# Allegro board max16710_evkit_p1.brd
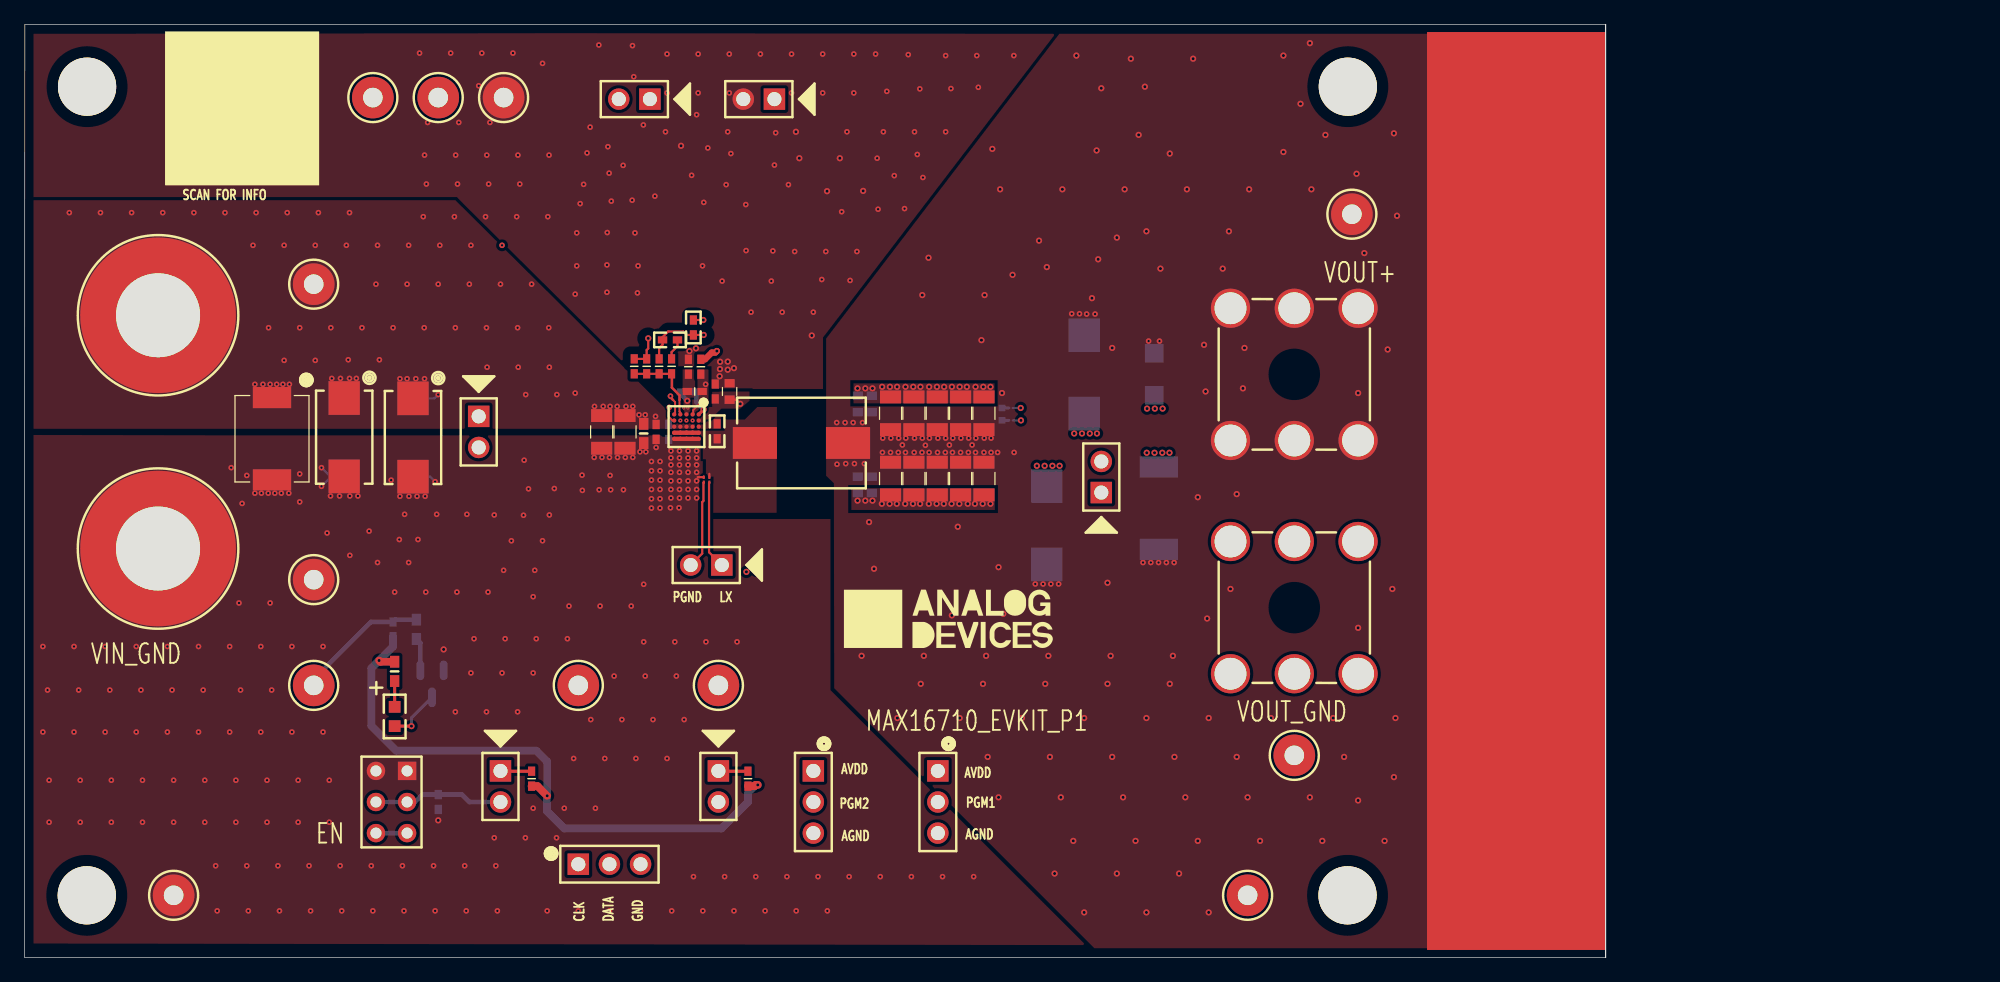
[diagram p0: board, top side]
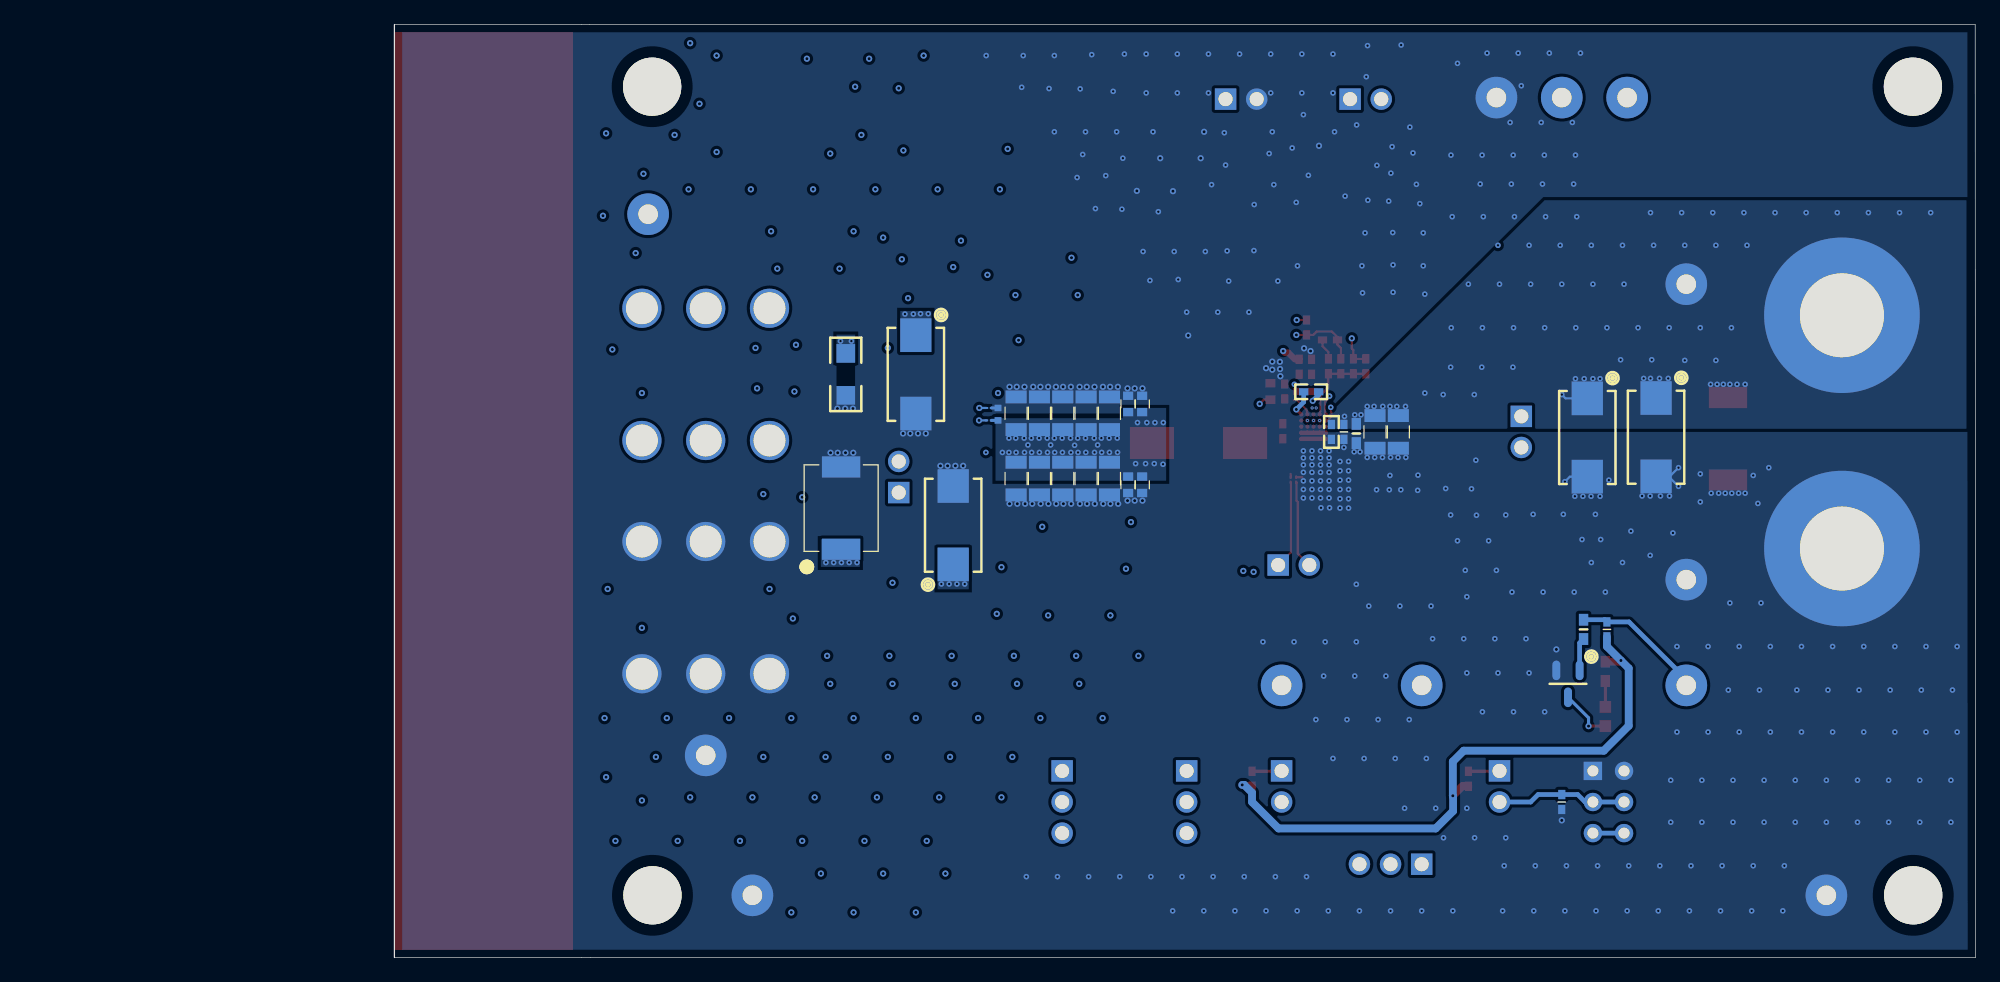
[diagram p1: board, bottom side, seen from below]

Outline 129.01 x 76.2 mm; copper layers: TOP, L2_PGND, L3_SIG_AGND, L4_SIG, L5_PGND, BOTTOM. Coordinates in mm from the lower left corner of the outline.
Outline path: 0,0 0.03,76.2 129.01,76.2 129.01,0 0,0

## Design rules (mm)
constraint set DEFAULT: min track width 0.178

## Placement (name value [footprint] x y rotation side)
C1  4.7UF  [0603]  57.53 46.23 270 top
C2  22UF  [1206]  49 42.93 90 top
C3  100UF  [1206]  78.28 39.12 90 bottom
C4  0.1UF  [0402]  56.36 46.23 270 top
C5  100UF  [1206]  72.57 39.12 90 bottom
C6  1UF  [0402]  54.69 46.23 0 top
C7  100UF  [1206]  74.47 44.45 270 bottom
C8  100UF  [1206]  72.57 44.45 270 bottom
C9  100UF  [1206]  72.57 44.45 270 top
C10  0.47UF  [0402]  56.52 42.98 90 top
C11  100UF  [1206]  72.57 39.12 90 top
C13  100UF  [1206]  70.66 44.45 270 top
C14  1UF  [0603#2]  50.52 42.8 90 top
C16  100UF  [1206]  70.66 39.12 90 top
C17  100PF  [0402]  49.75 48.28 270 top
C20  22UF  [1206]  47.09 42.93 90 top
C21  22UF  [1206]  49 42.93 90 bottom
C23  0.01UF  [0402]  52.67 50.44 0 top
C24  1UF  [0603#2]  50.52 42.8 90 bottom
C26  1000PF  [0402]  33.76 12.7 270 bottom
C27  4700PF  [0402]  52.55 42.93 90 bottom
C28  4700PF  [0402]  51.54 42.93 90 bottom
C29  0.1UF  [0402]  51.54 42.93 90 top
C30  22UF  [1206]  47.09 42.93 90 bottom
C31  470UF  [CAPMP7343X430M]  86.46 47.63 270 bottom
C32  100UF  [CAPMP7343X430M]  31.67 42.47 270 bottom
C33  100UF  [1206]  78.28 44.45 270 bottom
C34  100UF  [1206]  76.38 39.12 90 bottom
C35  100UF  [1206]  74.47 39.12 90 bottom
C36  100UF  [CAPMP7343X430M]  31.7 42.47 270 top
C37  100UF  [CAPMP7343X430M]  26.06 42.49 270 bottom
C39  100UF  [CAPMP7343X430M]  26.09 42.49 270 top
C40  470UF  [CAPMP7343X430M]  83.41 35.31 90 bottom
C41  47UF  [1206]  76.38 39.12 270 top
C43  47UF  [1206]  76.38 44.45 90 top
C44  47UF  [1206]  78.28 39.12 270 top
C46  100UF  [1206]  76.38 44.45 270 bottom
C47  0.1UF  [0402#2]  79.76 44.37 90 bottom
C48  100UF  [1206]  70.66 39.12 90 bottom
C49  47UF  [1206]  78.28 44.45 90 top
C50  100UF  [1206]  70.66 44.45 270 bottom
C51  10UF  [0603]  69.14 38.61 270 bottom
C52  10UF  [0603]  69.14 45.21 90 bottom
C53  10UF  [0603]  68 38.61 270 bottom
C54  100UF  [1206]  74.47 39.12 90 top
C55  100UF  [1206]  74.47 44.45 270 top
C72  10UF  [0603]  68 45.21 90 bottom
D1  MBRS540T3  [SOD9962X245M]  20.19 42.37 270 top
D3  MBRS540T3  [SOD9962X245M]  92.56 36.7 90 bottom
DS1  LGL29K-G2J1-24-Z  [LED_SMT160X080]  30.2 19.69 270 top
J1  PEC03SAAN  [SULLINS_PXC03SAAN]  74.52 15.24 270 top
J2  TSW-101-22-L-D  [SMTC_TSW-101-22-X-D]  61.19 70.1 90 top
J3  TSW-101-22-L-D  [SMTC_TSW-101-22-X-D]  51.03 70.1 90 top
J4  PEC03SAAN  [SULLINS_PXC03SAAN]  64.36 15.24 270 top
J5  6095  [KEYSTONE_6095]  10.9 52.45 0 top
J6  TSW-101-22-L-D  [SMTC_TSW-101-22-X-D]  38.84 15.24 180 top
J7  TSW-101-22-L-D  [SMTC_TSW-101-22-X-D]  56.62 15.24 180 top
J8  6095  [KEYSTONE_6095]  10.9 33.4 0 top
J9  PEC03SAAN  [SULLINS_PXC03SAAN]  45.19 7.62 0 top
J10  TSW-101-22-L-D  [SMTC_TSW-101-22-X-D]  37.06 44.2 180 top
J12  FINGERS_EVAL_NS  [EK_FINGERS_EVAL_NS]  121.72 38.1 90 top
J13  TSW-101-22-L-D  [SMTC_TSW-101-22-X-D]  56.9 32.05 90 top
J19  TSW-101-22-L-D  [SMTC_TSW-101-22-X-D]  87.86 37.97 0 top
L1  330NH  [IND_744308033]  63.39 42.02 0 top
MH1  9032  [KEYS_9032]  5.11 71.12 180 bottom
MH2  9032  [KEYS_9032]  5.08 5.08 180 bottom
MH3  9032  [KEYS_9032]  107.98 71.12 180 bottom
MH4  9032  [KEYS_9032]  107.95 5.08 180 bottom
NOREF  -  []  0 0 90 top
NOREF#2  -  []  163.3 35.56 0 top
NOREF#3  -  []  11.47 63.06 0 top
NOREF#4  -  []  54.08 168.91 0 top
NOREF#5  -  []  0 0 0 top
NOREF#6  -  []  -17.04 -57.15 0 top
NOREF#7  -  []  75.41 27.66 0 top
NOREF#8  -  []  -10.69 -44.45 0 top
NOREF#9  -  []  -17.04 -57.15 180 bottom
Q1  BSS138  [SOT95P237X112-3M]  33.25 22.35 270 bottom
R1  4.7  [0402]  55.18 48.25 270 top
R2  95.3  [0402]  54.2 46.2 0 bottom
R4  100  [1206#2]  92.18 47.63 270 bottom
R9  3K  [0402]  50.76 48.28 90 top
R11  0  [0402]  54.17 48.25 270 top
R13  3K  [0402]  51.78 48.28 90 top
R14  10  [0402]  54.57 51.46 90 top
R16  3K  [0402]  41.38 14.61 270 top
R17  3K  [0402]  59.03 14.61 270 top
R19  0  [0402]  52.8 48.28 270 top
R41  20K  [0402]  30.07 26.8 270 bottom
R42  100  [0603#2]  31.98 26.8 270 bottom
R51  210  [0603#2]  30.2 23.37 270 top
ST1  7808  [KEYSTONE_7808]  103.61 47.63 270 top
ST2  7808  [KEYSTONE_7808]  103.61 28.58 270 top
SU3  SX1100-B  [EVKIT_SHUNT]  103.48 79.08 0 top
SW1  GT21MCBE  [SW_GT21MCBE]  29.95 12.7 180 top
TP1  N/A  [KEYS_5011]  39.09 70.23 0 top
TP2  N/A  [KEYS_5011]  12.17 5.08 0 top
TP4  N/A  [KEYS_5010]  23.6 54.99 0 top
TP6  N/A  [KEYS_5126]  56.62 22.23 0 top
TP7  N/A  [KEYS_5011]  23.6 30.86 0 top
TP8  N/A  [KEYS_5010]  108.31 60.71 0 top
TP9  N/A  [KEYS_5011]  99.8 5.08 90 top
TP11  N/A  [KEYS_5011]  103.61 16.51 0 top
TP13  N/A  [KEYS_5012]  28.42 70.23 90 top
TP14  N/A  [KEYS_5012]  33.76 70.23 90 top
TP29  N/A  [KEYS_5126]  45.19 22.23 90 top
TP30  N/A  [KEYS_5126]  23.6 22.23 90 top
U1  MAX16710  [MAXIM_21-100614_SMD]  54.01 43.36 270 top
Y1  CONN_SENSE_POINT  [EK_CONN_SENSE_POINT]  80.49 44.88 0 bottom
Y2  CONN_SENSE_POINT  [EK_CONN_SENSE_POINT]  80.49 43.87 0 bottom
Y12  CONN_SENSE_POINT  [EK_CONN_SENSE_POINT]  55.42 39.01 90 top
Y15  CONN_SENSE_POINT  [EK_CONN_SENSE_POINT]  55.88 39.01 90 top

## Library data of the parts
C1 = CAP_NP: alternate symbols: 0603_NOSILK,CAPC1608X90L,CAP0603-NOT_FOR_TEST; part number: CAP_NP_0603CAP-0603,4.7UF,20-004U7-R1
C2 C20 C21 C30 = CAP_NP: alternate symbols: CAPC3216X90L; part number: CAP_NP_1206CAP-1206,22UF,20-0022U-EA83
C3 C5 C7-C9 C11 C13 C16 C33-C35 C46 C48 C50 C54 C55 = CAP_NP: alternate symbols: CAPC3216X90L; part number: CAP_NP_1206CAP-1206,100UF,EC111000002982
C4 = CAP_NP: alternate symbols: 0402_NOSILK,CAPC1005X50L; part number: CAP_NP_0402CAP-0402,0.1UF,20-000U1-19A
C6 = CAP_NP: alternate symbols: 0402_NOSILK,CAPC1005X50L,CAP0402-NOT_FOR_TEST; part number: CAP_NP_0402CAP-0402,1UF,20-0001U-19A
C10 = CAP_NP: alternate symbols: 0402_NOSILK,CAPC1005X50L,CAP0402-NOT_FOR_TEST; part number: CAP_NP_0402CAP-0402,0.47UF,20-00U47-CA50
C14 C24 = CAP_NP: alternate symbols: 0603_NOSILK,CAPC1608X90L,CAP0603-NOT_FOR_TEST; part number: CAP_NP_0603CAP-0603,1UF,20-0001U-P6
C17 = CAP_NP: alternate symbols: 0402_NOSILK,CAPC1005X50L,CAP0402-NOT_FOR_TEST; part number: CAP_NP_0402CAP-0402,100PF,EC111000001552
C23 = CAP_NP: alternate symbols: 0402_NOSILK,CAPC1005X50L,CAP0402-NOT_FOR_TEST; part number: CAP_NP_0402CAP-0402,0.01UF,20-00U01-B16
C26 = CAP_NP: alternate symbols: 0402_NOSILK,CAPC1005X50L; part number: CAP_NP_0402CAP-0402,1000PF,20-1000P-E7
C27 C28 = CAP_NP: alternate symbols: 0402_NOSILK,CAPC1005X50L; part number: CAP_NP_0402CAP-0402,4700PF,20-4700P-12
C29 C47 = CAP_NP: alternate symbols: 0402_NOSILK,CAPC1005X50L,CAP0402-NOT_FOR_TEST; part number: CAP_NP_0402CAP-0402,0.1UF,20-000U1-B68
C31 C40 = CAP_POL: alternate symbols: CAPMP7343X430L,CAPMP7343X430L_ALT,CAPMP7343X430M_1; part number: CAP_POL_7343CAP-CAPMP7343X430M,470UF,20-0470U-N2
C32 C36 C37 C39 = CAP_POL: part number: CAP_POL_7343CAP-CAPMP7343X430M,100UF,20-0100U-I9A
C41 C43 C44 C49 = CAP_NP: alternate symbols: CAPC3216X90L; part number: CAP_NP_1206CAP-1206,47UF,ECM1107
C51-C53 C72 = CAP_NP: alternate symbols: 0603_NOSILK,CAPC1608X90L; part number: CAP_NP_0603CAP-0603,10UF,20-0010U-CA02
D1 D3 = DIO_SCHOTTKY: alternate symbols: SOD7958X245L; part number: DIO_SCHOTTKY_SMC_CASE403-03-SOD9962X245M,MBRS540T3,30-MBRS540T3-00
DS1 = LED: alternate symbols: LED_SMT160X080_ALT; part number: LED_SMT160X080-LED_SMT160X080,LGL29K-G2J1-24-Z,30-LGL29KG2J124Z-00
J1 J4 J9 = HEADER_3P: alternate symbols: SULLINS_PXC03SL; part number: HEADER_3P_TH-SULLINS_PXC03SAAN,PEC03SAAN,01-PEC03SAAN3P-21
J2 J3 J6 J7 J10 J13 J19 = HEADER_1P_X_2R: part number: HEADER_1P_X_2R_TH-SMTC_TSW-101-22-X-D,TSW-101-22-L-D,01-TSW10122LD2P-19
J5 J8 = BANANA: alternate symbols: KEYSTONE_6095_LUG_HEAD,KEYSTONE_6095_LUG_NUT; part number: BANANA_TMR1-KEYSTONE_6095,6095,01-60952P-80
J12 = EK_FINGERS_EVAL_NS: part number: EK_FINGERS_EVAL_NS_EDGE-EK_FINGERS_EVAL_NS,FINGERS_EVAL_NS,N/A
L1 = INDUCT: part number: INDUCT_IND_744308033-IND_744308033,330NH,50-0330N-0LQ
MH1-MH4 = SPACER: part number: SPACER_MECH-02-SOM35016H-00,9032,KEYS_9032
Q1 = TRAN_NCH_3P: part number: TRAN_NCH_3P_SOT23-SOT95P237X112-3M,BSS138,90-BSS138-16
R1 = RES: alternate symbols: (0402_NOSILK,RESC1005X50L); part number: RES_0402RES-0402,4.7,80-004R7-23
R2 = RES: alternate symbols: (0402_NOSILK,RESC1005X50L); part number: RES_0402RES-0402,95.3,80-095R3-23
R4 = RES: part number: RES_1206RES-1206,100,80-0100R-Q5B
R9 R13 R16 R17 = RES: alternate symbols: (0402_NOSILK,RESC1005X50L); part number: RES_0402RES-0402,3K,80-0003K-23
R11 R19 = RES: alternate symbols: 0402_NOSILK,RESC1005X50L,RES0402-NOT_FOR_TEST; part number: RES_0402RES-0402,0,80-0000R-26B
R14 = RES: alternate symbols: 0402_NOSILK,RESC1005X50L,RES0402-NOT_FOR_TEST; part number: RES_0402RES-0402,10,80-0010R-23
R41 = RES: alternate symbols: 0402_NOSILK,RESC1005X50L,RES0402-NOT_FOR_TEST; part number: RES_0402RES-0402,20K,80-0020K-23
R42 = RES: alternate symbols: 0603_NOSILK,RESC1608X90L; part number: RES_0603RES-0603,100,80-0100R-24
R51 = RES: alternate symbols: (0603_NOSILK); part number: RES_0603RES-0603,210,80-0210R-24
ST1 ST2 = 7808: part number: 7808_CON-KEYSTONE_7808,7808,02-TTVER7808-00
SU3 = SHUNT: part number: SHUNT_SHUNT_2P-02-JMPFS1100B-00,SX1100-B,EVKIT_SHUNT
SW1 = GT21MCBE: part number: GT21MCBE_TH-SW_GT21MCBE,GT21MCBE,11-GT21MCBE-00
TP1 TP2 TP7 TP9 TP11 = TP: alternate symbols: TP_C340H160L; part number: TP_TP-KEYS_5011,N/A,02-TPMINI5011-00
TP4 TP8 = TP: alternate symbols: TP_C340H160L;KEYS_5010L; part number: TP_TP-KEYS_5010,N/A,02-TPMINI5010-00
TP6 TP29 TP30 = TP: part number: TP_TP-KEYS_5126,N/A,02-TPMULTI5126-00
TP13 TP14 = TP: part number: TP_TP-KEYS_5012,N/A,02-TPMINI5012-00
U1 = EK_MAX16710: part number: EK_MAX16710_WLP25-MAXIM_21-100614_SMD,MAX16710,N/A
Y1 Y2 Y12 Y15 = EK_CONN_SENSE_POINT: part number: EK_CONN_SENSE_POINT_SMD-EK_CONN_SENSE_POINT,CONN_SENSE_POINT,N/A

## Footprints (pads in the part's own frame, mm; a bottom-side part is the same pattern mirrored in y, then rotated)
0402
  rect 0.762x0.584 smd: 1(-0.61,0) 2(0.61,0)
0402#2
  rect 0.533x0.559 smd: 1(-0.508,0) 2(0.508,0)
0603
  rect 0.69x0.83 smd: 1(-0.67,0) 2(0.67,0)
0603#2
  rect 0.965x0.762 smd: 1(-0.787,0) 2(0.787,0)
1206
  rect 1.05x1.72 smd: 1(-1.335,0) 2(1.335,0)
1206#2
  rect 1.524x1.524 smd: 1(-1.714,0) 2(1.714,0)
CAPMP7343X430M
  rect 2.75x2.55 smd: 1(-3.2,0) 2(3.2,0)
EK_CONN_SENSE_POINT
  custom 0.04x0.04 smd: 1(-0.216,0) 2(0.216,0)
EK_FINGERS_EVAL_NS
  rect 74.93x14.567 smd: 1(0,0) 2(0,0)
IND_744308033
  rect 3.6x2.6 smd: 1(-3.8,0) 2(3.8,0)
KEYS_5010
  round 3.4 hole 1.6: 1(0,0)
KEYS_5011
  round 3.4 hole 1.6: 1(0,0)
KEYS_5012
  round 3.4 hole 1.6: 1(0,0)
KEYS_5126
  round 3.4 hole 1.6: 1(0,0)
KEYS_9032
  round 4.75 hole 4.75 unplated: (0,0)
KEYSTONE_6095
  round 12.7 hole 6.858: 1(0,0)
KEYSTONE_7808
  round 3.2 hole 2.6: 1(-5.4,5.205) 2(-5.4,0) 3(-5.4,-5.205) 4(5.4,5.205) 5(5.4,0) 6(5.4,-5.205)
LED_SMT160X080
  rect 0.96x0.96 smd: A(-0.787,0) K(0.787,0)
MAXIM_21-100614_SMD
  round 0.348 smd: A1(-1,1) A2(-0.5,1) A3(0,1) A4(0.5,1) A5(1,1) B1(-1,0.5) B2(-0.5,0.5) B3(0,0.5) B4(0.5,0.5) B5(1,0.5) C1(-1,0) C2(-0.5,0) C3(0,0) C4(0.5,0) C5(1,0) D1(-1,-0.5) D2(-0.5,-0.5) D3(0,-0.5) D4(0.5,-0.5) D5(1,-0.5) E1(-1,-1) E2(-0.5,-1) E3(0,-1) E4(0.5,-1) E5(1,-1)
SMTC_TSW-101-22-X-D
  rect 1.75x1.75 hole 1.15: 1(0,0)
  round 1.75 hole 1.15: 2(0,2.54)
SOD9962X245M
  rect 1.73x3.13 smd: A(3.36,0) C(-3.36,0)
SOT95P237X112-3M
  oval 1.6x0.65 smd: 1(-1.1,0.95) 2(-1.1,-0.95) 3(1.1,0)
SULLINS_PXC03SAAN
  rect 1.75x1.75 hole 1.15: 1(0,0)
  round 1.75 hole 1.15: 2(2.54,0) 3(5.08,0)
SW_GT21MCBE
  rect 1.5x1.5 hole 0.9: 1(-1.27,-2.54)
  round 1.5 hole 0.9: 2(-1.27,0) 3(-1.27,2.54) 4(1.27,-2.54) 5(1.27,0) 6(1.27,2.54)

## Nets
1.8V_VCC: C1.2 C4.2 J2.1 R1.1 R16.2 R17.2 R41.2 R51.1 U1.A2
AVDD: C6.2 J1.1 J3.1 J4.1 R1.2 U1.B1
GND_POWER: C1.1 C2.1 C3.1 C4.1 C5.1 C7.1 C8.1 C9.1 C11.1 C13.1 C14.1 C16.1 C20.1 C21.1 C24.1 C26.2 C27.1 C28.1 C29.1 C30.1 C31.2(B) C32.2(B) C33.1 C34.1 C35.1 C36.2(B) C37.2(B) C39.2(B) C40.2(B) C41.2 C43.2 C44.2 C46.1 C47.2 C48.1 C49.2 C50.1 C51.2 C52.2 C53.2 C54.1 C55.1 C72.2 D1.A D3.A J2.2 J8.1(P) J10.2 J12.2 J19.2 Q1.2(S) R4.2 R11.1 ST2.1 ST2.2 ST2.3 ST2.4 ST2.5 ST2.6 SW1.1 SW1.4 TP1.1(TP1) TP2.1(TP1) TP7.1(TP1) TP9.1(TP1) TP11.1(TP1) U1.A5 U1.B5 U1.C5 U1.D5 U1.E5 Y1.1 Y12.2(P2)
GND_SIGNAL: C6.1 J1.3 J3.2 J4.3 J9.3 R2.1 R11.2 U1.C1
VDDH: C2.2 C14.2 C20.2 C21.2 C24.2 C27.2 C28.2 C29.2 C30.2 C32.1 C36.1 C37.1 C39.1 D1.C(K) J5.1(P) J10.1 TP4.1(TP1) U1.B3 U1.C3 U1.D3 U1.E3
EN: J6.1 J9.1 R16.1 TP29.1(TP1) U1.E2
LX: C10.1 L1.1 U1.A4 U1.B4 U1.C4 U1.D4 U1.E4 Y15.2(P2)
PGM0: R2.2 U1.A1
PGM1: J1.2 U1.B2
PGM2: J4.2 J7.2 J9.2 U1.C2
PGOOD: R41.1 R42.1 TP30.1(TP1) U1.E1
UNNAMED_1_CAPNP_I109_1: C23.1 R13.2 R14.1 TP13.1(TP1)
UNNAMED_1_CAPNP_I109_2: C23.2 R19.1
UNNAMED_1_CAPNP_I259_2: C17.2 R9.1 R13.1 R19.2 U1.D1
UNNAMED_1_CAPNP_I293_2: C10.2 U1.A3
UNNAMED_1_EKCONNSENSEPOINT_I310_P1: J13.2 Y12.1
UNNAMED_1_EKCONNSENSEPOINT_I311_P1: J13.1 Y15.1
UNNAMED_4_CAPNP_I188_1: C26.1 J6.2 SW1.2 SW1.5
UNNAMED_4_GT21MCBE_I190_3: SW1.3 SW1.6
UNNAMED_4_HEADER1PX2R_I239_1: J7.1 R17.1 TP6.1(TP1)
UNNAMED_4_LED_I206_A: DS1.A R51.2
UNNAMED_4_LED_I206_B: DS1.K(B) Q1.3
UNNAMED_4_RESSMD_I203_2: Q1.1 R42.2
VOUT: C3.2 C5.2 C7.2 C8.2 C9.2 C11.2 C13.2 C16.2 C31.1 C33.2 C34.2 C35.2 C40.1 C41.1 C43.1 C44.1 C46.2 C47.1 C48.2 C49.1 C50.2 C51.1 C52.1 C53.1 C54.2 C55.2 C72.1 D3.C(K) J12.1 J19.1 L1.2 R4.1 ST1.1 ST1.2 ST1.3 ST1.4 ST1.5 ST1.6 TP8.1(TP1) Y2.1
VOUT_HF_CAP_N: C17.1 R9.2 U1.D2 Y1.2(P2)
VOUT_HF_CAP_P: R14.2 TP14.1(TP1) Y2.2(P2)

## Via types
v1: diameter 0.508, hole 0.254, TOP to BOTTOM, 189 vias
v2: diameter 0.457, hole 0.203, TOP to BOTTOM, 465 vias
v3: diameter 0.254, hole 0.127, TOP to BOTTOM, 5 vias

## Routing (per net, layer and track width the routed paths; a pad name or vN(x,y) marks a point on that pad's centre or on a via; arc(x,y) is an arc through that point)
1.8V_VCC: length 122.7
  TOP w0.178: 57.61,45.57 58.05,45.57 v1(58.4,45.22)
  TOP w0.508: v1(56.49,49.53) 56.36,49.4 56.08,49.4 55.53,48.86 R1.1
  TOP w0.635: R16.2 41.86,14 v1(42.65,13.21) ; v1(28.93,24.26) 29.03,24.16 R51.1 ; R17.2 59.56,14 59.66,14.1 v1(59.83,14.1)
  L3_SIG_AGND w0.178: J2.1 60.02,68.94 60.02,63.91 63.93,60 63.93,53.47 63.5,53.04 63.5,51.03 58.4,45.94 v1(58.4,45.22)
  L4_SIG w0.635: v1(56.49,49.53) 56.5,49.54 57.19,49.54 57.2,49.53 57.91,49.53 58.71,48.73 58.71,47.33 58.4,47.03 v1(58.4,45.22) 62.08,41.54 62.08,19.3 59.83,17.06 v1(59.83,14.1)
  BOTTOM w0.635: R41.2 30.07,25.4 v1(28.93,24.26) 28.3,23.62 28.3,18.92 30.33,16.89 41.76,16.89 42.65,16 v1(42.65,13.21) 42.62,13.19 42.62,11.96 44.04,10.54 56.87,10.54 59.03,12.7 59.03,13.46 59.66,14.1 v1(59.83,14.1)
AVDD: length 87.1
  TOP w0.152: U1.B1 54.56,44.4 54.56,44.7 55.4,45.54 55.63,45.54
  L3_SIG_AGND w0.178: v2(55.58,46.81) 55.6,46.84 55.6,48.43 55.89,48.72 55.89,49.26 55.9,49.27 55.89,49.28 55.89,49.78 56.24,50.13 58.11,50.13 60.27,52.29 60.27,61.58 56.71,65.14 51.51,65.14 49.91,66.73 49.91,68.99 J3.1
  L3_SIG_AGND w0.254: v2(55.58,46.81) 55.7,46.81 57.43,45.08 57.43,43.59 63.93,37.08 63.93,23.29 71.98,15.24 J1.1
  L4_SIG w0.381: J4.1 J1.1
GND_POWER: length 75.6
  TOP w0.178: Y12.2 54.93,39.23
  TOP w0.348: U1.E5 U1.D5 U1.C5 U1.B5 U1.A5
  L3_SIG_AGND w0.178: v1(57.89,48.13) 57.89,47.38 58.06,47.2 59.07,47.2 63.03,51.16 63.03,53.23 63.51,53.71 63.51,59.83 59.6,63.74 59.6,69.15 J2.2
  L4_SIG w0.178: J19.2 86.97,40.51 85.57,39.12 82.63,39.12 81.8,39.95 81.8,41.72 79.67,43.85 71.06,43.85 70.61,44.3 v1(70.61,46.61) ; v2(51.54,41.66) 51.16,41.66 50.3,42.51 38.16,42.51 38.12,42.55 37.95,42.55 J10.2
  BOTTOM w0.178: v2(33.5,38.86) 33.1,39.27 C32.2 ; 25.04,39.29 C37.2 ; 25.04,39.29 24.94,39.29 v2(24.23,40.01) ; 25.04,39.29 v2(24.23,38.48)
  BOTTOM w0.254: C47.2 Y1.1
  vias: v1(33.76,11.2) v1(34.2,25.16) v1(53.57,66.29) v1(54.25,49.53) v1(54.78,49.75) v1(56.74,48.06) v1(56.72,47.47) v1(56.76,48.65) v1(57.38,48.67) v1(57.38,48.01) v1(62.94,67.44) v1(63.22,65.28) v1(64.24,50.8) v1(65.48,62.59) v1(66.52,65.28) v1(67.97,46.48) v1(67.97,37.31) v1(68.43,62.61) v1(68.61,46.48) v1(68.61,37.31) v1(69.19,46.48) v1(69.19,37.31) v1(69.95,37.06) v1(69.98,46.61) v1(70.59,37.06) v1(71.2,46.61) v1(71.17,37.06) v1(71.86,37.06) v1(71.88,46.61) v1(72.52,46.61) v1(72.49,37.06) v1(73.1,46.61) v1(73.08,37.06) v1(73.81,46.61) v1(73.79,37.06) v1(74.45,46.61) v1(74.42,37.06) v1(75.03,46.61) v1(75.01,37.06) v1(75.64,37.06) v1(75.67,46.61) v1(76.3,46.61) v1(76.28,37.06) v1(76.89,46.61) v1(76.96,37.06) v1(77.55,37.06) v1(77.6,46.61) v1(78.23,46.61) v1(78.18,37.06) v1(78.82,46.61) v1(78.82,37.06) v1(82.6,40.16) v1(83.24,40.16) v1(83.87,40.16) v1(84.45,40.16) v1(85.65,42.8) v1(86.28,42.8) v1(86.92,42.8) v1(87.5,42.8) v1(91.59,44.83) v1(91.57,41.22) v1(92.23,44.83) v1(92.2,41.22) v1(92.84,41.22) v1(92.86,44.83) v1(93.42,41.22) v2(1.5,25.4) v2(1.5,18.42) v2(1.88,21.84) v2(2.01,14.48) v2(2.01,11.05) v2(4.04,25.4) v2(4.04,18.42) v2(4.42,21.84) v2(4.55,14.48) v2(4.55,11.05) v2(6.58,25.4) v2(6.58,18.42) v2(6.96,21.84) v2(7.09,14.48) v2(7.09,11.05) v2(9.12,25.4) v2(9.12,18.42) v2(9.5,21.84) v2(9.63,14.48) v2(9.63,11.05) v2(11.66,25.4) v2(11.66,18.42) v2(12.04,21.84) v2(12.17,14.48) v2(12.17,11.05) v2(14.2,25.4) v2(14.2,18.42) v2(14.58,21.84) v2(14.71,14.48) v2(14.71,11.05) v2(15.6,7.49) v2(15.72,3.81) v2(16.74,25.4) v2(16.74,18.42) v2(16.87,40.01) v2(17.25,14.48) v2(17.25,11.05) v2(17.5,28.96) v2(17.63,21.84) v2(17.75,37.08) v2(18.14,39.37) v2(18.14,7.49) v2(18.26,3.81) v2(18.8,37.92) v2(19.33,37.92) v2(19.28,25.4) v2(19.28,18.42) v2(19.79,14.48) v2(19.79,11.05) v2(19.89,37.92) v2(20.04,28.96) v2(20.17,21.84) v2(20.42,37.92) v2(20.68,7.49) v2(20.8,3.81) v2(20.95,37.92) v2(21.56,37.92) v2(21.82,25.4) v2(21.82,18.42) v2(22.33,14.48) v2(22.33,11.05) v2(22.45,39.5) v2(22.45,37.21) v2(23.22,7.49) v2(23.34,3.81) v2(24.36,25.4) v2(24.36,18.42) v2(24.69,34.67) v2(24.87,14.48) v2(24.87,11.05) v2(24.97,37.69) v2(25.7,37.69) v2(25.76,7.49) v2(25.88,3.81) v2(26.54,37.69) v2(26.54,32.84) v2(27.2,37.69) v2(28.12,34.82) v2(28.3,7.49) v2(28.42,3.81) v2(28.8,32.26) v2(29.92,38.99) v2(30.2,29.85) v2(30.63,37.67) v2(30.58,34.14) v2(30.84,7.49) v2(31.01,36.2) v2(30.96,3.81) v2(31.34,32.26) v2(31.37,37.67) v2(32.03,37.67) v2(32.11,34.14) v2(32.23,73.86) v2(32.64,65.53) v2(32.69,37.67) v2(32.74,29.85) v2(32.79,63.17) v2(32.89,68.2) v2(33.38,7.49) v2(33.5,3.81) v2(33.63,36.2) v2(34.77,73.86) v2(35.15,20.07) v2(35.18,65.53) v2(35.33,63.17) v2(35.28,29.85) v2(35.43,68.2) v2(35.92,7.49) v2(36.04,3.81) v2(36.09,36.2) v2(36.42,23.24) v2(36.68,26.04) v2(37.06,71.2) v2(37.31,73.86) v2(37.62,60.5) v2(37.72,65.53) v2(37.69,20.07) v2(37.82,29.85) v2(37.87,63.17) v2(37.97,68.2) v2(38.33,36.14) v2(38.33,9.78) v2(38.46,7.49) v2(38.58,3.81) v2(38.96,58.17) v2(38.96,23.24) v2(39.09,31.62) v2(39.22,26.04) v2(39.73,34.04) v2(39.85,73.86) v2(40.16,60.5) v2(40.23,20.07) v2(40.26,65.53) v2(40.41,63.17) v2(40.72,36.12) v2(40.77,40.61) v2(40.87,9.78) v2(41.12,38.28) v2(41.5,29.46) v2(41.5,23.24) v2(41.5,12.19) v2(41.63,31.62) v2(41.76,26.04) v2(42.27,73.03) v2(42.27,34.04) v2(42.65,3.81) v2(42.7,60.5) v2(42.8,65.53) v2(42.82,36.14) v2(43.23,38.3) v2(43.41,9.78) v2(44.04,12.19) v2(44.3,26.04) v2(44.42,28.7) v2(44.81,16.26) v2(44.93,54.18) v2(45.06,59.18) v2(45.06,56.49) v2(45.19,3.81) v2(45.34,61.57) v2(45.49,39.4) v2(45.52,38.15) v2(45.62,63.14) v2(45.9,65.71) v2(46.15,67.82) v2(46.2,19.43) v2(46.48,40.84) v2(46.58,12.19) v2(46.86,74.52) v2(46.89,38.2) v2(46.96,28.7) v2(47.12,40.84) v2(47.35,16.26) v2(47.55,59.21) v2(47.52,56.57) v2(47.52,54.33) v2(47.6,66.22) v2(47.7,64.06) v2(47.73,40.84) v2(47.73,3.81) v2(47.78,39.37) v2(47.83,38.2) v2(47.88,61.77) v2(48.11,22.99) v2(48.39,40.84) v2(48.74,19.43) v2(48.84,64.69) v2(48.87,38.2) v2(49.02,40.84) v2(49.5,28.7) v2(49.61,74.47) v2(49.58,61.85) v2(49.63,40.84) v2(49.71,71.93) v2(49.81,59.18) v2(49.89,16.26) v2(50.01,54.28) v2(50.06,56.49) v2(50.22,41.3) v2(50.27,3.81) v2(50.5,68) v2(50.52,30.48) v2(50.52,25.78) v2(50.65,22.99) v2(50.7,41.3) v2(51.16,40.51) v2(51.16,39.75) v2(51.16,38.99) v2(51.16,38.23) v2(51.16,37.47) v2(51.16,36.7) v2(51.28,19.43) v2(51.44,62.18) v2(51.85,40.51) v2(51.85,39.75) v2(51.85,38.99) v2(51.85,38.23) v2(51.85,37.47) v2(51.85,36.7) v2(52.3,67.44) v2(52.43,73.79) v2(52.43,70.61) v2(52.43,16.26) v2(52.74,41.38) v2(52.74,40.81) v2(52.74,40.23) v2(52.74,39.62) v2(52.74,38.93) v2(52.74,38.23) v2(52.74,37.53) v2(52.7,36.73) v2(52.81,3.81) v2(53.06,25.78) v2(53.19,22.99) v2(53.44,41.38) v2(53.44,40.81) v2(53.44,40.23) v2(53.44,39.62) v2(53.44,38.93) v2(53.44,38.23) v2(53.44,37.53) v2(53.4,36.73) v2(53.82,19.43) v2(54.14,41.38) v2(54.14,40.81) v2(54.14,40.23) v2(54.14,39.62) v2(54.14,38.93) v2(54.14,38.23) v2(54.14,37.53) v2(54.43,63.88) v2(54.58,6.6) v2(54.84,68.83) v2(54.84,41.38) v2(54.84,40.81) v2(54.84,40.23) v2(54.84,39.62) v2(54.84,38.93) v2(54.84,38.23) v2(54.84,37.53) v2(54.97,73.79) v2(54.97,70.61) v2(55.32,56.49) v2(55.35,3.81) v2(55.42,61.67) v2(55.6,25.78) v2(55.75,66.12) v2(56.92,55.25) v2(57.12,6.6) v2(57.25,63.12) v2(57.38,67.44) v2(57.51,73.79) v2(57.51,70.61) v2(57.63,65.66) v2(57.89,3.81) v2(58.14,25.78) v2(58.85,61.49) v2(58.88,57.73) v2(59.28,52.71) v2(59.66,6.6) v2(60.05,73.79) v2(60.43,3.81) v2(60.93,55.25) v2(61.06,57.71) v2(61.19,64.72) v2(61.29,67.36) v2(61.82,52.71) v2(62.2,6.6) v2(62.33,63.12) v2(62.59,73.79) v2(62.59,70.61) v2(62.84,57.66) v2(62.97,3.81) v2(64.36,52.71) v2(64.74,6.6) v2(65.05,55.37) v2(65.13,73.79) v2(65.13,70.61) v2(65.38,57.66) v2(65.51,3.81) v2(66.67,60.91) v2(67.11,67.44) v2(67.28,6.6) v2(67.36,55.3) v2(67.67,73.79) v2(67.67,70.61) v2(67.92,57.66) v2(69.44,73.79) v2(69.57,65.28) v2(69.65,61.11) v2(69.82,6.6) v2(70.08,67.44) v2(70.36,70.74) v2(70.97,63.86) v2(71.81,61.16) v2(72.11,73.74) v2(72.36,6.6) v2(72.62,67.44) v2(72.85,65.58) v2(73.05,70.94) v2(73.3,63.7) v2(74.9,6.6) v2(75.16,73.66) v2(75.16,67.44) v2(75.59,70.97) v2(77.44,6.6) v2(77.7,73.66) v2(77.83,71.07) v2(80.72,73.66)
GND_SIGNAL: length 107.6
  L3_SIG_AGND w0.178: 55.02,46.61 55.02,47.09 55.09,47.17 55.09,48.51 55.47,48.89 55.47,49.95 56.07,50.55 57.93,50.55 59.86,52.47 59.86,61.4 56.54,64.72 51.33,64.72 49.49,66.56 49.49,69.1 J3.2
  L3_SIG_AGND w0.635: J1.3 J4.3 56.62,10.16 54.08,7.62 J9.3 50.27,12.07 42.93,19.4 42.93,23.53 43.07,23.67 43.07,33.82 43.62,34.38 43.62,36.48 42.01,38.09 42.01,45.89 43.03,46.9 46.34,46.9
  BOTTOM w0.381: R2.1 53.59,45.95 v1(54.08,45.47)
  vias: v3(53.8,44.88) v3(54.13,44.88)
VDDH: length 17.7
  L4_SIG w0.178: J10.1 38.33,42.93 50.14,42.93 51.41,44.2 v2(51.49,44.2)
  BOTTOM w0.178: C32.1 33.45,45.67 v2(33.76,45.97)
  vias: v2(3.66,60.83) v2(6.2,60.83) v2(8.74,60.83) v2(11.28,60.83) v2(13.82,60.83) v2(16.36,60.83) v2(18.64,58.17) v2(18.8,46.81) v2(18.9,60.83) v2(19.46,46.81) v2(19.91,51.44) v2(20.04,46.81) v2(20.57,46.81) v2(21.08,46.81) v2(21.18,58.17) v2(21.18,48.77) v2(21.44,60.83) v2(21.62,46.81) v2(22.45,51.44) v2(23.72,58.17) v2(23.72,48.77) v2(23.98,60.83) v2(24.99,51.44) v2(25.07,47.29) v2(25.78,47.29) v2(26.26,58.17) v2(26.42,48.82) v2(26.52,60.83) v2(26.52,47.29) v2(27.08,47.29) v2(27.53,51.44) v2(28.68,54.99) v2(28.8,58.17) v2(28.96,48.82) v2(30.07,51.44) v2(30.63,47.27) v2(31.22,54.99) v2(31.22,47.27) v2(31.34,58.17) v2(31.93,47.27) v2(32.54,60.5) v2(32.61,51.44) v2(32.64,47.27) v2(33.76,54.99) v2(33.88,58.17) v2(35.08,60.5) v2(35.15,51.44) v2(36.3,54.99) v2(36.42,58.17) v2(37.69,51.44) v2(37.74,48.21) v2(38.84,54.99) v2(40.23,51.44) v2(40.28,48.21) v2(40.89,45.97) v2(41.38,54.99) v2(42.77,51.44) v2(42.82,48.21) v2(43.43,45.97) v2(44.93,46.1) v2(46.51,45.01) v2(47.22,45.01) v2(47.78,45.01) v2(48.36,45.01) v2(49.07,45.01) v2(49.63,45.01) v2(50.14,44.32) v2(50.65,44.32)
EN: length 53.9
  TOP w0.152: U1.E2 52.87,43.86 52.56,44.17 52.56,44.54 52.61,44.59 v2(52.61,44.93)
  TOP w0.254: R16.1 38.9,15.21 arc(38.86,15.22) J6.1
  L4_SIG w0.254: J9.1 45.19,9.7 39.65,15.24 J6.1 38.84,16.51 44.55,22.23 TP29.1 52.45,29.49 52.45,33.22 55.89,36.66 55.89,41.81 55.28,42.43 53.95,42.43 52.98,43.39 52.98,44.56 v2(52.61,44.93)
LX: length 2.3
  TOP w0.178: Y15.2 55.88,39.5
  TOP w0.348: U1.E4 U1.D4 U1.C4 U1.B4 U1.A4
PGM0: length 2.3
  TOP w0.254: U1.A1 v1(55.42,44.76)
  BOTTOM w0.381: v1(55.42,44.76) 54.81,45.36 R2.2
PGM1: length 41.1
  L3_SIG_AGND w0.254: J1.2 73.25,13.97 71.22,13.97 61.7,23.5 61.7,29.62 v1(59.74,31.57)
  L4_SIG w0.254: v3(54.51,43.86) 54.95,43.42 55.69,43.42 56.88,42.22 56.88,41.48 59.74,38.63 v1(59.74,31.57)
PGM2: length 56.1
  L3_SIG_AGND w0.254: J7.2 61.19,17.27 61.19,29.21 v1(58.9,31.5)
  L4_SIG w0.254: J4.2 J7.2 51.54,12.7 47.73,8.89 J9.2 ; v1(58.9,31.5) 58.9,38.46 56.39,40.97 56.39,42.02 55.48,42.93 54.43,42.93 54.01,43.35 v3(54.01,43.86)
PGOOD: length 61.9
  TOP w0.152: U1.E1 53.09,44.43 53.09,45.36 52.91,45.54
  TOP w0.203: v2(52.7,45.85) 52.7,45.75 52.91,45.54
  L4_SIG w0.203: TP30.1 28.3,26.92 38.11,26.92 46.25,35.06 53.2,35.06 55.42,37.29 55.42,41.62 55.08,41.96 53.39,41.96 52.3,43.05 52.3,44.43 52.04,44.7 52.04,45.17 52.18,45.32 52.18,45.33 v2(52.7,45.85)
  BOTTOM w0.381: TP30.1 24.23,22.86 24.23,23.37 28.27,27.41 R41.1 30.25,27.58 R42.1
UNNAMED_1_CAPNP_I109_1: length 55.8
  TOP w0.178: v1(55.41,50.85) R14.1 54.03,50.85 53.75,51.13 52.52,51.13 52.06,50.67 C23.1 52.06,50.05 51.78,49.77 R13.2
  L3_SIG_AGND w0.178: v1(55.41,50.85) 55.41,50.99 55.98,51.56 57.38,51.56 58.14,52.32 58.14,60.83 55.8,63.17 47.42,63.17 42.65,67.94 42.65,71.25 41,72.9 31.72,72.9 30.84,72.01 30.84,71.12 29.95,70.23 TP13.1
UNNAMED_1_CAPNP_I109_2: length 1.7
  TOP w0.178: C23.2 53.28,49.93 52.8,49.44 R19.1
UNNAMED_1_CAPNP_I259_2: length 6.7
  TOP w0.152: 53.44,45.54 53.44,44.58 53.51,44.51 U1.D1
  TOP w0.178: R19.2 R13.1 R9.1 C17.2
  TOP w0.203: R19.2 52.82,47.64 52.82,46.54 53.44,45.92 53.44,45.54
UNNAMED_1_EKCONNSENSEPOINT_I310_P1: length 7.2
  TOP w0.178: J13.2 55.3,32.99 55.3,37.2 55.4,37.3 55.4,38.77 Y12.1
UNNAMED_1_EKCONNSENSEPOINT_I311_P1: length 7.2
  TOP w0.178: Y15.1 55.85,38.77 55.85,33.1 J13.1
UNNAMED_4_CAPNP_I188_1: length 10.7
  BOTTOM w0.381: SW1.5 SW1.2 31.85,12.7 32.46,13.31 C26.1 35.69,13.31 36.3,12.7 J6.2
UNNAMED_4_GT21MCBE_I190_3: length 2.5
  BOTTOM w0.381: SW1.6 SW1.3
UNNAMED_4_HEADER1PX2R_I239_1: length 9.4
  TOP w0.254: J7.1 56.64,15.21 R17.1
  L4_SIG w0.254: J7.1 TP6.1
UNNAMED_4_LED_I206_A: length 2.1
  TOP w0.254: DS1.A R51.2
UNNAMED_4_LED_I206_B: length 4.4
  TOP w0.254: DS1.K v1(31.57,18.9)
  BOTTOM w0.254: v1(31.57,18.9) 31.57,19.58 Q1.3
UNNAMED_4_RESSMD_I203_2: length 2.7
  BOTTOM w0.381: R42.2 32.3,25.69 Q1.1
VOUT: length 21.9
  L4_SIG w0.178: J19.1 86.46,37.97 85.83,38.61 82.55,38.61 81.38,39.77 81.38,41.55 79.49,43.43 70.95,43.43 70.69,43.18 v2(70.69,42.42)
  BOTTOM w0.254: Y2.1 C47.1
  vias: v1(68.3,24.64) v1(68.91,35.56) v1(69.32,31.75) v1(70.59,27.94) v1(71.22,19.56) v1(73.13,22.35) v1(73.25,54.1) v1(73.38,24.64) v1(73.76,57.15) v1(75.67,27.94) v1(76.15,35.18) v1(76.3,19.56) v1(78.08,50.42) v1(78.21,22.35) v1(78.33,54.1) v1(78.46,24.64) v1(78.59,16.38) v1(78.97,66.04) v1(79.48,31.88) v1(79.48,13.08) v1(79.6,62.74) v1(79.76,46.1) v1(79.86,28.07) v1(80.62,55.75) v1(81.38,19.56) v1(82.78,58.55) v1(83.29,22.35) v1(83.41,56.39) v1(83.54,24.64) v1(83.67,16.38) v1(84.05,6.86) v1(84.56,13.08) v1(84.68,62.74) v1(85.57,9.53) v1(85.83,73.66) v1(86.46,19.56) v1(86.46,3.68) v1(87.1,53.85) v1(87.48,65.91) v1(87.6,57.02) v1(87.86,70.99) v1(88.37,30.61) v1(88.37,22.35) v1(88.62,24.64) v1(88.75,49.78) v1(88.75,16.38) v1(89.13,58.8) v1(89.13,6.86) v1(89.64,13.08) v1(89.76,62.74) v1(90.27,73.41) v1(90.65,9.53) v1(90.91,67.18) v1(91.41,71.12) v1(91.54,59.31) v1(91.54,19.56) v1(91.54,3.68) v1(92.68,56.26) v1(93.45,65.66) v1(93.45,22.35) v1(93.7,24.64) v1(93.83,16.38) v1(94.21,6.86) v1(94.72,13.08) v1(94.84,62.74) v1(95.35,73.41) v1(95.73,37.59) v1(95.73,9.53) v1(96.24,50.04) v1(96.37,46.23) v1(96.49,27.69) v1(96.62,19.56) v1(96.62,3.68) v1(97.76,56.26) v1(98.27,59.31) v1(98.4,30.1) v1(98.91,37.85) v1(98.91,16.38) v1(99.42,46.48) v1(99.54,49.78) v1(99.8,13.08) v1(99.92,62.74) v1(100.81,9.53) v1(101.7,19.56) v1(102.72,73.66) v1(102.72,65.79) v1(104.11,69.72) v1(104.88,74.68) v1(104.88,13.08) v1(105,62.74) v1(105.89,9.53) v1(106.15,67.18) v1(106.78,19.56) v1(107.67,16.38) v1(108.69,64.01) v1(108.81,46.1) v1(108.81,26.92) v1(108.81,12.83) v1(109.32,57.53) v1(110.97,9.53) v1(111.23,49.66) v1(111.61,30.1) v1(111.73,67.31) v1(111.73,14.73) v1(111.86,19.56) v1(111.99,60.58) v2(66.27,43.69) v2(66.29,40.28) v2(66.95,43.69) v2(67.01,40.34) v2(67.61,43.69) v2(67.72,40.34) v2(68.38,43.69) v2(68.53,40.34) v2(70.03,42.42) v2(70,41.25) v2(70.66,41.25) v2(71.32,42.42) v2(71.3,41.25) v2(71.63,41.86) v2(71.91,42.42) v2(71.88,41.25) v2(72.62,42.42) v2(72.59,41.25) v2(73.25,42.42) v2(73.23,41.25) v2(73.51,41.83) v2(73.84,42.42) v2(73.81,41.25) v2(74.52,42.42) v2(74.5,41.25) v2(75.13,41.25) v2(75.16,42.42) v2(75.46,41.86) v2(75.74,42.42) v2(75.72,41.25) v2(76.4,42.42) v2(76.38,41.25) v2(77.04,42.42) v2(77.01,41.25) v2(77.32,41.86) v2(77.62,42.42) v2(77.6,41.25) v2(78.31,42.42) v2(78.28,41.25) v2(78.87,42.42) v2(78.87,41.25) v2(79.4,41.25) v2(80.75,41.25) v2(82.47,30.51) v2(83.11,30.51) v2(83.74,30.51) v2(84.38,30.51) v2(85.45,52.58) v2(86.08,52.58) v2(86.66,52.55) v2(87.35,52.55) v2(91.26,32.26) v2(91.72,50.34) v2(91.9,32.26) v2(92.53,32.26) v2(92.61,50.34) v2(93.17,32.26) v2(93.8,32.26)
VOUT_HF_CAP_N: length 63.7
  TOP w0.178: v1(50.89,50.57) 50.89,49.74 50.76,49.61 R9.2 C17.1
  L4_SIG w0.178: 54.7,45.72 54.7,44.7 54.31,44.31 53.82,44.31 53.51,44 v3(53.51,43.86)
  L4_SIG w0.203: 54.7,45.72 54.7,46.62 53.09,48.23 53.09,50.04 52.56,50.57 v1(50.89,50.57)
  L4_SIG w0.254: v1(81.28,44.88) 81.94,45.54 81.94,56.74 79.26,59.42 55.74,59.42 51.89,55.58 51.89,52.25 50.89,51.25 v1(50.89,50.57)
  BOTTOM w0.178: Y1.2 v1(81.28,44.88)
VOUT_HF_CAP_P: length 99.8
  TOP w0.178: R14.2 v1(55.39,52.06)
  L3_SIG_AGND w0.178: TP14.1 32.17,70.23 31.28,71.12 31.28,71.82 31.91,72.45 40.81,72.45 42.2,71.06 42.2,68.27 42.23,68.24 42.23,67.77 47.25,62.75 55.59,62.75 57.69,60.65 57.69,52.51 57.25,52.06 v1(55.39,52.06)
  L4_SIG w0.254: v1(81.31,43.87) 80.64,44.53 80.64,45.14 81.38,45.88 81.38,56.6 79.06,58.93 55.95,58.93 52.45,55.43 52.45,52.43 52.81,52.06 v1(55.39,52.06)
  BOTTOM w0.178: Y2.2 v1(81.31,43.87)

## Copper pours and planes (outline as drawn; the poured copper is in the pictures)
1.8V_VCC on TOP: 54.91,43.69 55.35,43.69 55.63,43.94 55.96,43.94 56.46,44.45 56.87,44.83 58.39,44.83 59.16,45.47 59.16,46.23 56.11,46.23 56.11,44.96 55.73,44.96 54.84,44.07 54.84,43.76
AVDD on TOP: 55.8,48.03 54.89,48.03 54.89,47.19 54.91,47.17 54.91,45.64 54.41,45.64 54.41,44.2 54.58,44.2 55.12,44.73 55.35,44.73 55.8,45.19
GND_POWER on TOP: 67.46,38.33 67.46,36.55 79.17,36.55 79.17,38.33
GND_POWER on TOP: 44.35,52.78 35.28,62.1 0.74,62.1 0.74,75.44 44.3,75.49 84.25,75.44 65.28,50.7 65.28,46.43 50.65,46.43 ; 1 cut-out
GND_POWER on TOP: 67.64,45.26 67.64,46.89 79.15,46.89 79.15,45.26
GND_POWER on TOP: 65.76,35.81 65.76,21.84 86.59,1.02 0.74,1.14 0.74,42.67 16.1,42.65 51.92,42.65 52.03,42.53 53.01,42.53 55.02,42.52 55.17,42.37 55.17,40.54 55.35,40.54 55.34,39.46 55.2,39.32 55.18,36.01 55.37,35.81
GND_POWER on BOTTOM: 128.37,75.56 128.37,0.64 0.64,0.64 0.66,45.87 0.66,75.56 ; 1 cut-out
GND_POWER on L2_PGND: 0.66,75.56 128.37,75.56 128.37,0.64 0.64,0.64 ; 3 cut-outs
GND_POWER on L5_PGND: 128.37,75.56 128.37,0.64 0.64,0.64 0.66,75.56 ; 3 cut-outs
GND_SIGNAL on TOP: 54.15,44.27 53.97,44.27 53.67,44.58 53.7,46.74 53.7,48.03 54.61,48.03 54.61,47.29 54.71,47.19 54.71,45.72 54.33,45.72 54.33,44.45
GND_SIGNAL on L3_SIG_AGND: 45.69,60.33 57.25,60.33 57.25,52.07 54.71,49.53 54.71,47.24 57.12,44.83 57.12,43.94 45.69,43.94 ; 1 cut-out
VDDH on TOP: 0.74,61.85 35.15,61.85 52.81,44.32 52.81,43.82 52.93,43.66 54.71,43.66 54.71,43.18 0.74,43.18
VDDH on BOTTOM: 0.74,61.85 35.15,61.85 52.81,44.32 52.81,43.18 0.74,43.18
VDDH on L4_SIG: 0.74,61.85 35.15,61.85 52.81,44.32 52.81,43.18 0.74,43.18 ; 1 cut-out
LX on TOP: 54.87,43.03 57.12,43.03 57.12,43.94 58.78,43.94 59.79,44.96 61.39,44.96 61.37,36.32 55.6,36.32 55.6,40.69 55.35,40.69 55.35,42.49 55.17,42.67 54.87,42.68
UNNAMED_1_CAPNP_I293_2 on TOP: 56.82,44.15 56.36,44.15 56.03,43.82 55.7,43.82 55.4,43.54 54.84,43.54 54.84,43.18 56.82,43.18
VOUT on TOP: 84.43,75.44 128.24,75.44 128.24,0.76 87.29,0.76 66.07,22 66.04,38.74 65.41,39.34 65.41,50.55
VOUT on BOTTOM: 91.03,34.16 91.03,31.9 94.21,31.9 94.21,34.16
VOUT on BOTTOM: 91.41,48.64 91.41,50.88 92.94,50.88 92.94,48.64
VOUT on BOTTOM: 82.14,33.4 82.14,30.07 84.68,30.07 84.68,33.4
VOUT on BOTTOM: 66.04,44.88 69.57,44.88 69.57,44.04 79.96,44.04 79.96,38.94 66.04,38.94
VOUT on BOTTOM: 85.19,49.66 85.19,52.81 87.73,52.81 87.73,49.66
VOUT on L3_SIG_AGND: 84.43,75.44 128.24,75.44 128.24,0.76 112.6,0.76 112.6,2.16 85.93,2.13 66.14,21.97 66.14,26.29 66.13,29.34 66.01,51.31
VOUT on L4_SIG: 84.43,75.44 128.24,75.44 128.24,0.76 87.29,0.76 66.14,21.97 66.01,51.31 ; 1 cut-out

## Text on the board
Ref Des/Silkscreen Top: PGND | LX | PGM2 | AVDD | AGND | PGM1 | CLK | DATA | GND | VIN_GND | EN | MAX16710_EVKIT_P1 | VOUT_GND | VOUT+
User.22: NOTES: | SURFACE FINISH: | TESTING: | SOLDERMASK: | MISCELLANEOUS: | SILKSCREEN: | MATERIAL: | TOOLING: | 16.  VENDOR LOGO & DATE CODE REQUIREMENT.  DATE CODE FORMAT MUST BE YYWW ONLY | 17.  FINAL ELECTRICAL TEST TO BE PERFORMED USING PROVIDED IPC-D-356A NETLIST OR ODB++ FORMAT FILE. | 18.  A TIME DOMAIN REFLECTOMETER REPORT FOR EACH IMPEDANCE CONTROLLED LAYER AND A CERTIFICATE | 19. IF PRESENT, ALL BLIND/BURIED VIAS WITH AN ASPECT RATIO <1:1 TO BE PLATED SHUT WITH COPPER WHEN | 20.  FOR ALL DRILL INFORMATION REFER TO DRILL CHART. | 21.  FINISHED SURFACE CONTACTS AND FILLED VIAS TO BE FREE OF ANY PITS. SCRATCHES PROBE MARKS | 23.  PEMNUT | 14.  SOLDERMASK OVER BARE COPPER OR BARE GOLD (BOTH SIDES) WITH LIQUID PHOTO IMAGEABLE (LPI) INK | 13.  DRILL SIZES ARE FINISHED HOLE SIZES. ALL HOLES SHALL BE LOCATED WITHIN .005 DTP,UNLESS SPECIFIED. | 22.  THIEVING: | 9.  ALL TRACES FILLETED OPTION TO ENHANCE RELIABILITY AT PAD JUNCTIONS | 10.  LAYER TO LAYER REGISTRATIONS SHALL BE WITHIN .003 INCHES. | 15. APPLY SILKSCREEN USING A NON-CONDUCTIVE EPOXY INK | 11.  FINISHED COPPER WEIGHT/THICKNESS: | 12. USE CHECKED ITEMS FOR PLATING | 3.  THE PCB SHALL BE FABRICATED TO IPC-6012, TYPE X, CLASS 2. | 4.  BOARD MATERIAL & CONSTRUCTION SHALL MEET THE REQUIREMENTS OF UL796 | 5.  OVERALL BOARD THICKNESS REFER TO LAMINATION DIAGRAM. TOLERANCE APPLIES | 6.  BOW & TWIST NOT TO EXCEED 0.0075 IN. (0.75%) PER LINEAR INCH. | 7.  PHOTO ETCH CIRCUITRY PER ENCLOSED GERBER RS274X OR ODB++ FORMAT FILE. | 8.  IMPEDANCE REQUIREMENTS: IF NO STACKUP IS DEFINED, THE VENDOR IS ALLOWED TO ADJUST THE DIELECTRIC | 1.  DIMENSIONS ARE IN INCHES (EXCEPT WHERE NOTED). | 2.  BOARD MATERIAL: | (X)  FINGERS TO BE GOLD PLATED. | (X)  FINISH CONDUCTOR SURFACES: IMMERSION GOLD, 1.58-3.94 MICRO INCHES OVER | (X)  WHITE | ( )  OTHER ________________________ | (X)  REFER TO LAMINATION DIAGRAM FOR FINISHED COPPER WEIGHT/THICKNESS REQUIREMENTS. | (X)  PLACE ON BOTTOM LEGEND LAYER. IF NO BOTTOM LEGEND SUPPLIED, CREATE BOTTOM LEGEND LAYER TO ADD. | ( )  PLACE ON TOP LEGEND LAYER. IF NO TOP LEGEND SUPPLIED,CREATE TOP LEGEND LAYER TO ADD. | ( )  ELECTRODEPOSITED HARD GOLD PLATE, TYPE 1 (99.7% MIN GOLD), GRADE C | (X)  OTHER _________GREEN SOLDER MASK | ( )  CUSTOM MAXIM TEAL SOLDER MASK. PANTONE #326C. | MINIMUM BARREL PLATING OF .001 IN. PLATED HOLES SHALL NOT BE ROUGH OR IRREGULAR SO AS TO | HINDER PROPER SOLDER WICKING. BARREL RELIEF ON SOLDERMASK ALLOWED ON UNFILLED VIA IN PAD HOLES. | USED AS VIA-IN PAD OR AS A STACKED VIA. BLIND/BURIED VIAS WITH AN ASPECT RATIO >1:1 TO BE FILLED | WITH NON-CONDUCTIVE EPOXY. UNLESS OTHERWISE SPECIFIED. | (X)  NON-CONDUCTIVE EPOXY. FILL AND CAP ALL 0.005  INCH DRILLED VIAS. | ( )  SILVER. FILL AND CAP ALL 0.XXXX INCH DRILLED VIAS. | IF PRESENT,DO NOT MODIFY SOLDERMASK DEFINED PADS (MASK OPENINGS LESS THAN COPPER PAD) WITHOUT APPROVAL. | (REQUIRED UNLESS OTHERWISE SPECIFIED IN QUOTE) | THE PCB SHALL HAVE A VERIFICATION STAMP. | OR OTHER DEFORMITIES THAT COULD EFFECT THE APPERANCE AND PERFORMACE OF THE CONTACT | SURFACE. CONTACTS ARE TO BE AS FLAT AS POSSIBLE. NOT TO EXCEED +/- 0.001" OF FLATNESS. | OF COMPLIANCE SHALL BE PROVIDED BY VENDOR AT TIME OF SHIPMENT. INSTANCES WHERE TDR TESTING | CAN'T BE PERFORMED BECAUSE THE TRACE LENGTH IS TOO SHORT ON THE OUTER LAYERS AT THE PIN ESCAPES | IS ACCEPTABLE, ALL OTHER INSTANCES MUST BE REPORTED. | ( )  SUPPLIER MAY ADD THIEVING TO COMPENSATE FOR LOW COPPER DENSITY AREAS ON THIS DESIGN. | WHERE SPACING PERMITS. | LEGEND TO LEGEND +/- 0.007 INCHES | (X)  SUPPLIER MAY NOT ADD THIEVING TO COMPENSATE FOR LOW COPPER DENSITY AREAS ON THIS DESIGN. | ( )  PEMNUTS TO BE INSTALLED BY FABRICATOR.. | ( )  PEMNUTS NOT TO BE INSTALLED BY FABRICATOR. | (X)  NOT APPLICABLE. | ( )  FILLETED | (X)  NOT FILLETED | (X)  ISOLA 370HR OR EQUIVALENT | ( )  NELCO-4000-13 | ( )  MEGTRON 6 | ( )  ROGERS 4350B | ( )  ROGERS 4003C | ( )  ISOLA-FR408HR OR EQUIVALENT | WORKMANSHIP SHALL CONFORM TO IPC-A-600, CLASS 2, CURRENT REVISIONS. | WITH FLAMMABILITY RATING OF 94V-O. | AFTER ALL LAMINATION AND PLATING PROCESSES. IT IS TO BE MEASURED FROM | TOP PCB METAL TO BOTTOM PCB METAL UNLESS OTHERWISE SPECIFIED. | BOW & TWIST SHOULD BE MEASURED PER IPC-TM-650, METHOD 2.4.22. | DRILL LOCATION AND SIZE CONTROLLED BY EXCELLON CNC DRILL FILE. | THICKNESS AND TRACE WIDTHS TO MEET THE IMPEDANCE REQUIREMENT. IF SPECIFIED, VENDOR MUST FOLLOW AND | MEET THE REQUIREMENTS LISTED IN THE IMPEDANCE TABLE. ANY ADJUSTMENTS MADE TO THE DEFINED STACKUP, | TRACE WIDTH & SPACING THAT IMPACT THE REQUIREMENTS MUST HAVE WRITTEN APPROVAL FROM MAXIM. | UNLESS OTHERWISE SPECIFIED | (USE CHECKED ITEMS FOR MATERIAL) | (KNOOP HARDNESS 130-200), CLASS 1 (50-100 MICRO INCHES THICK) IN ACCORDANCE WITH MIL-G-45204C. | GENERAL SURFACING REQUIREMENTS MUST MEET ANSI/IPC-A-600(CURRENT REV) SECTION 4.0, | CLASS 3 (50-100 MICROINCHES THICK) OVER ELECTRODEPOSITED NICKEL PLATE | IN ACCORDANCE WITH ANSI/IPC-A-600D, SECTION 4.0, CLASS 3 (200-600 MICROINCHES THICK). | 118-236 MICRO INCHES MINIMUM OF ELECTROLESS NICKEL. | THE STARTING COPPER WEIGHT/THICKNESS CAN VARY AS LONG AS THE FINISHED COPPER | WEIGHT/THICKNESS IS NOT LESS THAN THE SPECIFIED VALUE, UNLESS OTHERWISE SPECIFIED. | UNLESS OTHERWISE SPECIFIED: | MAX16710_EVKIT_P1
User.26: FIGURE | SIZE | 5.0 | 8.0 | 10.0 | 35.43 | 45.28 | 62.99 | 102.36 | 270.0 | 187.01 | TOLERANCE | +3.0/-3.0 | +3.0/-6.0 | +3.0/-8.0 | PLATED | NON-PLATED | ALL UNITS ARE IN MILS | QTY | 5 | 465 | 189 | 6 | 23 | 12 | 2 | 4 | NOTES | DRILL CHART: TOP to BOTTOM
